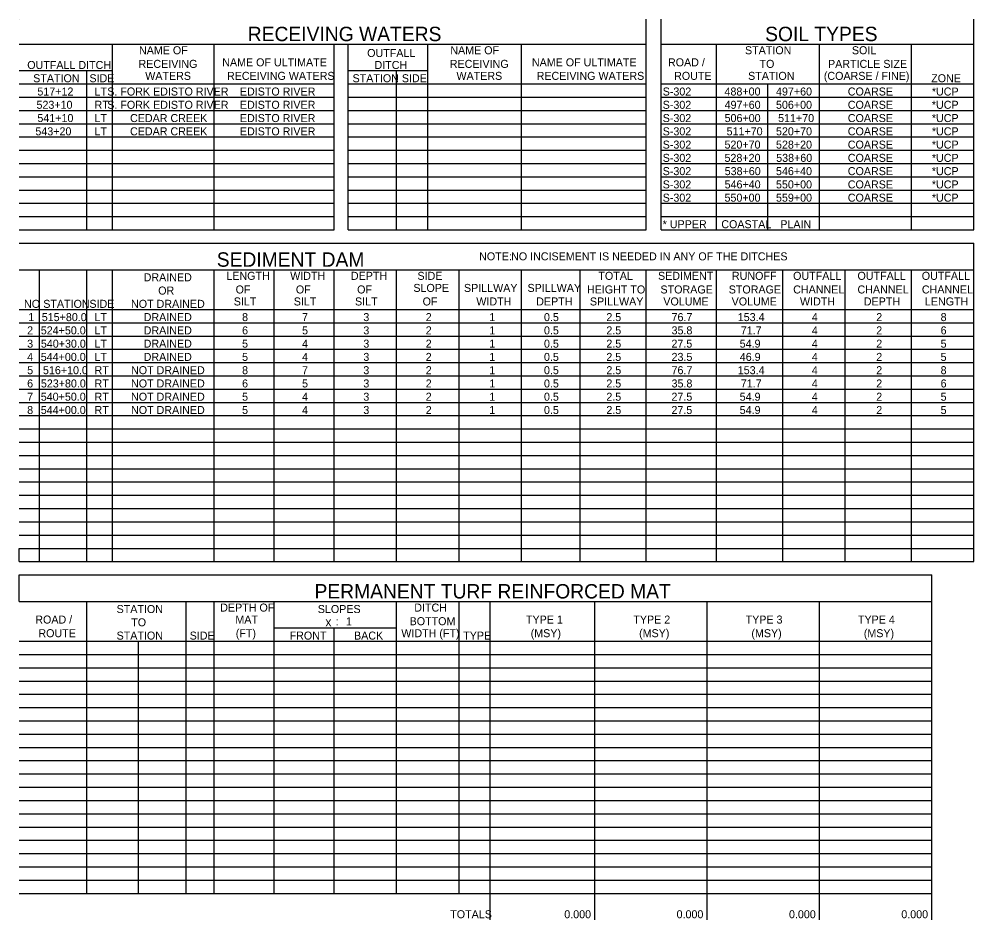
# Model space of a CAD drawing. Extents: x 17139 to 21295, y 12843 to 18076.
# Drawn here: x 19644 to 20688, y 12843 to 13827 of the extents above; entities that cross this region are included whole.
import ezdxf

# ---------------------------------------------------------------- set-up
doc = ezdxf.new("R2010")
doc.units = 0
doc.layers.add('Level 1', color=7, linetype='Continuous')
doc.layers.add('Level 3', color=7, linetype='Continuous')

msp = doc.modelspace()

# ---------------------------------------------------------------- linework, layer by layer
at = {"layer": 'Level 1'}
for p, q in [((20330.2, 13596.6), (20330.2, 13826.9)), ((20346.4, 13596.6), (20346.4, 13826.9)), ((20688.4, 13596.6), (20688.4, 13826.9)), ((19644.4, 13799.6), (20330.2, 13799.6)), ((19746.7, 13596.6), (19746.7, 13799.6)), ((19857.6, 13596.6), (19857.6, 13799.6)), ((19989, 13596.6), (19989, 13799.6)), ((20004.3, 13596.6), (20004.3, 13799.6)), ((20091.3, 13596.6), (20091.3, 13799.6)), ((20193.7, 13596.6), (20193.7, 13799.6)), ((20346.4, 13799.6), (20688.4, 13799.6)), ((20406.9, 13596.6), (20406.9, 13799.6)), ((20519.5, 13596.6), (20519.5, 13799.6)), ((20620.2, 13596.6), (20620.2, 13799.6)), ((19644.4, 13770.6), (19746.7, 13770.6)), ((19718.6, 13596.6), (19718.6, 13770.6)), ((20004.3, 13770.6), (20091.3, 13770.6)), ((20057.2, 13596.6), (20057.2, 13770.6)), ((19644.4, 13756.1), (19989, 13756.1)), ((19644.4, 13756.1), (19718.6, 13756.1)), ((20004.3, 13756.1), (20330.2, 13756.1)), ((20004.3, 13756.1), (20057.2, 13756.1)), ((20346.4, 13756.1), (20688.4, 13756.1)), ((20463.2, 13596.6), (20463.2, 13756.1)), ((19644.4, 13741.6), (19989, 13741.6)), ((20004.3, 13741.6), (20330.2, 13741.6)), ((20346.4, 13741.6), (20688.4, 13741.6)), ((19644.4, 13727.1), (19989, 13727.1)), ((20004.3, 13727.1), (20330.2, 13727.1)), ((20346.4, 13727.1), (20688.4, 13727.1)), ((19644.4, 13712.6), (19989, 13712.6)), ((20004.3, 13712.6), (20330.2, 13712.6)), ((20346.4, 13712.6), (20688.4, 13712.6)), ((19644.4, 13698.1), (19989, 13698.1)), ((20004.3, 13698.1), (20330.2, 13698.1)), ((20346.4, 13698.1), (20688.4, 13698.1)), ((19644.4, 13683.6), (19989, 13683.6)), ((20004.3, 13683.6), (20330.2, 13683.6)), ((20346.4, 13683.6), (20688.4, 13683.6)), ((19644.4, 13669.1), (19989, 13669.1)), ((20004.3, 13669.1), (20330.2, 13669.1)), ((20346.4, 13669.1), (20688.4, 13669.1)), ((19644.4, 13654.6), (19989, 13654.6)), ((20004.3, 13654.6), (20330.2, 13654.6)), ((20346.4, 13654.6), (20688.4, 13654.6)), ((19644.4, 13640.1), (19989, 13640.1)), ((20004.3, 13640.1), (20330.2, 13640.1)), ((20346.4, 13640.1), (20688.4, 13640.1)), ((19644.4, 13625.6), (19989, 13625.6)), ((20004.3, 13625.6), (20330.2, 13625.6)), ((20346.4, 13625.6), (20688.4, 13625.6)), ((19644.4, 13611.1), (19989, 13611.1)), ((20004.3, 13611.1), (20330.2, 13611.1)), ((20346.4, 13611.1), (20688.4, 13611.1)), ((19644.4, 13596.6), (19989, 13596.6)), ((20004.3, 13596.6), (20330.2, 13596.6)), ((20346.4, 13596.6), (20688.4, 13596.6)), ((19644.4, 13582.1), (20688.4, 13582.1)), ((20688.4, 13234.1), (20688.4, 13582.1)), ((19644.4, 13553.1), (20688.4, 13553.1)), ((19666.6, 13234.1), (19666.6, 13553.1)), ((19718.6, 13234.1), (19718.6, 13553.1)), ((19746.7, 13234.1), (19746.7, 13553.1)), ((19857.6, 13234.1), (19857.6, 13553.1)), ((19923.3, 13234.1), (19923.3, 13553.1)), ((19989, 13234.1), (19989, 13553.1)), ((20057.2, 13234.1), (20057.2, 13553.1)), ((20125.4, 13234.1), (20125.4, 13553.1)), ((20193.7, 13234.1), (20193.7, 13553.1)), ((20257.7, 13234.1), (20257.7, 13553.1)), ((20330.2, 13234.1), (20330.2, 13553.1)), ((20406.9, 13234.1), (20406.9, 13553.1)), ((20479.4, 13234.1), (20479.4, 13553.1)), ((20547.7, 13234.1), (20547.7, 13553.1)), ((20620.2, 13234.1), (20620.2, 13553.1)), ((19644.4, 13509.6), (20688.4, 13509.6)), ((19857.6, 13509.6), (20688.4, 13509.6)), ((19644.4, 13495.1), (20688.4, 13495.1)), ((19644.4, 13480.6), (20688.4, 13480.6)), ((19644.4, 13466.1), (20688.4, 13466.1)), ((19644.4, 13451.6), (20688.4, 13451.6)), ((19644.4, 13437.1), (20688.4, 13437.1)), ((19644.4, 13422.6), (20688.4, 13422.6)), ((19644.4, 13408.1), (20688.4, 13408.1)), ((19644.4, 13393.6), (20688.4, 13393.6)), ((19644.4, 13379.1), (20688.4, 13379.1)), ((19644.4, 13364.6), (20688.4, 13364.6)), ((19644.4, 13350.1), (20688.4, 13350.1)), ((19644.4, 13335.6), (20688.4, 13335.6)), ((19644.4, 13321.1), (20688.4, 13321.1)), ((19644.4, 13306.6), (20688.4, 13306.6)), ((19644.4, 13292.1), (20688.4, 13292.1)), ((19644.4, 13277.6), (20688.4, 13277.6)), ((19644.4, 13263.1), (20688.4, 13263.1)), ((19644.4, 13234.1), (19644.4, 13248.6)), ((19644.4, 13248.6), (20688.4, 13248.6)), ((19644.4, 13234.1), (20688.4, 13234.1)), ((19644.4, 13190.6), (19644.4, 13219.6)), ((19644.4, 13219.6), (20642.3, 13219.6)), ((20642.3, 12842.6), (20642.3, 13219.6)), ((19644.4, 13190.6), (20642.3, 13190.6)), ((19718.6, 12871.6), (19718.6, 13190.6)), ((19826.9, 12871.6), (19826.9, 13190.6)), ((19857.6, 12871.6), (19857.6, 13190.6)), ((19923.3, 12871.6), (19923.3, 13190.6)), ((20057.2, 12871.6), (20057.2, 13190.6)), ((20125.4, 12871.6), (20125.4, 13190.6)), ((20159.6, 12842.6), (20159.6, 13190.6)), ((20273.9, 12842.6), (20273.9, 13190.6)), ((20396.7, 12842.6), (20396.7, 13190.6)), ((20519.5, 12842.6), (20519.5, 13190.6)), ((19923.3, 13161.6), (20057.2, 13161.6)), ((19989, 12871.6), (19989, 13161.6)), ((19644.4, 13147.1), (20642.3, 13147.1)), ((19774.9, 12871.6), (19774.9, 13147.1)), ((19826.9, 13147.1), (20057.2, 13147.1)), ((20057.2, 13147.1), (20642.3, 13147.1)), ((19644.4, 13132.6), (20642.3, 13132.6)), ((19644.4, 13118.1), (20642.3, 13118.1)), ((19644.4, 13103.6), (20642.3, 13103.6)), ((19644.4, 13089.1), (20642.3, 13089.1)), ((19644.4, 13074.6), (20642.3, 13074.6)), ((19644.4, 13060.1), (20642.3, 13060.1)), ((19644.4, 13045.6), (20642.3, 13045.6)), ((19644.4, 13031.1), (20642.3, 13031.1)), ((19644.4, 13016.6), (20642.3, 13016.6)), ((19644.4, 13002.1), (20642.3, 13002.1)), ((19644.4, 12987.6), (20642.3, 12987.6)), ((19644.4, 12973.1), (20642.3, 12973.1)), ((19644.4, 12958.6), (20642.3, 12958.6)), ((19644.4, 12944.1), (20642.3, 12944.1)), ((19644.4, 12929.6), (20642.3, 12929.6)), ((19644.4, 12915.1), (20642.3, 12915.1)), ((19644.4, 12900.6), (20642.3, 12900.6)), ((19644.4, 12886.1), (20642.3, 12886.1)), ((19644.4, 12871.6), (20642.3, 12871.6))]:
    msp.add_line(p, q, dxfattribs=at)
at = {"layer": 'Level 3'}
msp.add_line((19644.4, 13826.9), (19644.4, 13826.9), dxfattribs=at)

# ---------------------------------------------------------------- texts
at = {"layer": 'Level 1'}
for s, height, p in [('RECEIVING WATERS', 15.747, (19894.4, 13802.8)), ('SOIL TYPES', 15.75, (20460.1, 13802.8)), ('NAME OF ', 8.75, (19775.5, 13788.5)), ('OUTFALL', 8.75, (20025, 13785.5)), ('NAME OF ', 8.75, (20115.9, 13788.5)), ('STATION ', 8.75, (20438.1, 13788.5)), ('SOIL ', 8.75, (20555, 13788.5)), ('OUTFALL DITCH', 8.748, (19653.3, 13772.4)), ('RECEIVING', 8.75, (19775, 13773.6)), ('NAME OF ULTIMATE ', 8.748, (19866.5, 13775.3)), ('DITCH', 8.75, (20033, 13772.4)), ('RECEIVING', 8.75, (20115.3, 13773.6)), ('NAME OF ULTIMATE ', 8.748, (20205.1, 13775.3)), ('ROAD / ', 8.75, (20353.9, 13775.3)), ('TO ', 8.75, (20454, 13773.6)), ('PARTICLE SIZE', 8.748, (20528.9, 13773.6)), ('STATION', 8.75, (19659.8, 13757.9)), ('SIDE', 8.75, (19721.3, 13757.9)), ('WATERS', 8.75, (19782.3, 13760.5)), ('RECEIVING WATERS', 8.748, (19871.7, 13760.5)), ('STATION', 8.75, (20009, 13757.9)), ('SIDE', 8.75, (20062.9, 13757.9)), ('WATERS', 8.75, (20122.6, 13760.5)), ('RECEIVING WATERS', 8.748, (20210.3, 13760.5)), ('ROUTE', 8.75, (20360.6, 13760.5)), ('STATION', 8.75, (20441.5, 13760.5)), ('(COARSE / FINE)', 8.748, (20524.3, 13760.5)), ('ZONE', 8.75, (20641.7, 13757.9)), ('517+12', 8.75, (19664.4, 13743.4)), ('LT', 8.75, (19726.9, 13743.4)), ('S. FORK EDISTO RIVER', 8.748, (19740.8, 13743.4)), ('EDISTO RIVER', 8.748, (19885.8, 13743.4)), ('S-302', 8.75, (20348.1, 13743.4)), ('488+00', 8.75, (20415.7, 13743.4)), ('497+60', 8.75, (20472, 13743.4)), ('COARSE', 8.75, (20550.5, 13743.4)), ('*UCP', 8.75, (20642.4, 13743.4)), ('523+10', 8.75, (19663.4, 13728.9)), ('RT', 8.75, (19726.9, 13728.9)), ('S. FORK EDISTO RIVER', 8.748, (19740.8, 13728.9)), ('EDISTO RIVER', 8.748, (19885.8, 13728.9)), ('S-302', 8.75, (20348.1, 13728.9)), ('497+60', 8.75, (20415.8, 13728.9)), ('506+00', 8.75, (20472, 13728.9)), ('COARSE', 8.75, (20550.5, 13728.9)), ('*UCP', 8.75, (20642.4, 13728.9)), ('541+10', 8.75, (19664.4, 13714.4)), ('LT', 8.75, (19726.9, 13714.4)), ('CEDAR CREEK', 8.748, (19765.7, 13714.4)), ('EDISTO RIVER', 8.748, (19885.8, 13714.4)), ('S-302', 8.75, (20348.1, 13714.4)), ('506+00', 8.75, (20415.8, 13714.4)), ('511+70', 8.75, (20474.3, 13714.4)), ('COARSE', 8.75, (20550.5, 13714.4)), ('*UCP', 8.75, (20642.4, 13714.4)), ('543+20', 8.75, (19662.2, 13699.9)), ('LT', 8.75, (19726.9, 13699.9)), ('CEDAR CREEK', 8.748, (19765.7, 13699.9)), ('EDISTO RIVER', 8.748, (19885.8, 13699.9)), ('S-302', 8.75, (20348.1, 13699.9)), ('511+70', 8.75, (20418, 13699.9)), ('520+70', 8.75, (20472, 13699.9)), ('COARSE', 8.75, (20550.5, 13699.9)), ('*UCP', 8.75, (20642.4, 13699.9)), ('S-302', 8.75, (20348.1, 13685.4)), ('520+70', 8.75, (20415.7, 13685.4)), ('528+20', 8.75, (20472, 13685.4)), ('COARSE', 8.75, (20550.5, 13685.4)), ('*UCP', 8.75, (20642.4, 13685.4)), ('S-302', 8.75, (20348.1, 13670.9)), ('528+20', 8.75, (20415.7, 13670.9)), ('538+60', 8.75, (20472.2, 13670.9)), ('COARSE', 8.75, (20550.5, 13670.9)), ('*UCP', 8.75, (20642.4, 13670.9)), ('S-302', 8.75, (20348.1, 13656.4)), ('538+60', 8.75, (20415.9, 13656.4)), ('546+40', 8.75, (20472, 13656.4)), ('COARSE', 8.75, (20550.5, 13656.4)), ('*UCP', 8.75, (20642.4, 13656.4)), ('S-302', 8.75, (20348.1, 13641.9)), ('546+40', 8.75, (20415.8, 13641.9)), ('550+00', 8.75, (20472, 13641.9)), ('COARSE', 8.75, (20550.5, 13641.9)), ('*UCP', 8.75, (20642.4, 13641.9)), ('S-302', 8.75, (20348.1, 13627.4)), ('550+00', 8.75, (20415.7, 13627.4)), ('559+00', 8.75, (20472, 13627.4)), ('COARSE', 8.75, (20550.5, 13627.4)), ('*UCP', 8.75, (20642.4, 13627.4)), ('* UPPER', 8.75, (20348.1, 13598.4)), ('COASTAL', 8.75, (20412.2, 13598.4)), ('PLAIN', 8.75, (20476.7, 13598.4)), ('SEDIMENT DAM          ', 15.747, (19860.5, 13556.3)), ('NOTE:', 8.75, (20147.4, 13563.3)), (' NO INCISEMENT IS NEEDED IN ANY OF THE DITCHES', 8.748, (20179.1, 13563.3)), ('DRAINED', 8.75, (19780.6, 13540.4)), ('LENGTH', 8.75, (19871, 13542)), ('WIDTH', 8.75, (19940.8, 13542)), ('DEPTH', 8.75, (20007.2, 13542)), ('SIDE', 8.75, (20080, 13542)), ('TOTAL', 8.75, (20277.8, 13542)), ('SEDIMENT', 8.75, (20343, 13542)), ('RUNOFF', 8.75, (20423.8, 13542)), ('OUTFALL', 8.75, (20490.7, 13542)), ('OUTFALL', 8.75, (20561.1, 13542)), ('OUTFALL', 8.75, (20631.4, 13542)), ('OR', 8.75, (19796.5, 13525.9)), (' OF ', 8.75, (19877.9, 13527.1)), ('OF ', 8.75, (19947, 13527.1)), ('OF ', 8.75, (20014, 13527.1)), ('SLOPE', 8.75, (20075.5, 13528.8)), ('SPILLWAY ', 8.75, (20130.8, 13528.8)), ('SPILLWAY', 8.75, (20200.3, 13528.8)), ('HEIGHT TO', 8.75, (20265.3, 13527.1)), ('STORAGE', 8.75, (20345.7, 13527.1)), ('STORAGE', 8.75, (20420.3, 13527.1)), ('CHANNEL', 8.75, (20490.8, 13527.1)), ('CHANNEL', 8.75, (20561.1, 13527.1)), ('CHANNEL', 8.75, (20631.5, 13527.1)), ('NO', 8.75, (19649.8, 13511.4)), ('STATION', 8.75, (19670.8, 13511.4)), ('SIDE', 8.75, (19721.3, 13511.4)), ('NOT DRAINED', 8.748, (19766.8, 13511.4)), ('SILT', 8.75, (19879.1, 13514)), ('SILT', 8.75, (19944.7, 13514)), ('SILT', 8.75, (20011.7, 13514)), ('OF', 8.75, (20085.6, 13514)), ('WIDTH', 8.75, (20144.3, 13514)), ('DEPTH', 8.75, (20209.8, 13514)), ('SPILLWAY', 8.75, (20268.5, 13514)), ('VOLUME', 8.75, (20348.8, 13514)), ('VOLUME', 8.75, (20423.5, 13514)), ('WIDTH', 8.75, (20498.2, 13514)), ('DEPTH', 8.75, (20568, 13514)), ('LENGTH', 8.75, (20634.8, 13514)), ('1', 8.75, (19654.4, 13496.9)), ('515+80.0', 8.75, (19669.2, 13496.9)), ('LT', 8.75, (19726.9, 13496.9)), ('DRAINED', 8.75, (19780.6, 13496.9)), ('8', 8.75, (19888.2, 13496.9)), ('7', 8.75, (19953.8, 13496.9)), ('3', 8.75, (20020.8, 13496.9)), ('2', 8.75, (20089, 13496.9)), ('1', 8.75, (20158.5, 13496.9)), ('0.5', 8.75, (20218.3, 13496.9)), ('2.5', 8.75, (20286.5, 13496.9)), ('76.7', 8.75, (20357.8, 13496.9)), ('153.4', 8.75, (20430.2, 13496.9)), ('4', 8.75, (20511.2, 13496.9)), ('2', 8.75, (20581.6, 13496.9)), ('8', 8.75, (20652, 13496.9)), ('2', 8.75, (19653.2, 13482.4)), ('524+50.0', 8.75, (19668.1, 13482.4)), ('LT', 8.75, (19726.9, 13482.4)), ('DRAINED', 8.75, (19780.6, 13482.4)), ('6', 8.75, (19888.2, 13482.4)), ('5', 8.75, (19953.8, 13482.4)), ('3', 8.75, (20020.8, 13482.4)), ('2', 8.75, (20089, 13482.4)), ('1', 8.75, (20158.5, 13482.4)), ('0.5', 8.75, (20218.3, 13482.4)), ('2.5', 8.75, (20286.5, 13482.4)), ('35.8', 8.75, (20357.8, 13482.4)), ('71.7', 8.75, (20433.5, 13482.4)), ('4', 8.75, (20511.2, 13482.4)), ('2', 8.75, (20581.6, 13482.4)), ('6', 8.75, (20652, 13482.4)), ('3', 8.75, (19653.2, 13467.9)), ('540+30.0', 8.75, (19668.2, 13467.9)), ('LT', 8.75, (19726.9, 13467.9)), ('DRAINED', 8.75, (19780.6, 13467.9)), ('5', 8.75, (19888.2, 13467.9)), ('4', 8.75, (19953.8, 13467.9)), ('3', 8.75, (20020.8, 13467.9)), ('2', 8.75, (20089, 13467.9)), ('1', 8.75, (20158.5, 13467.9)), ('0.5', 8.75, (20218.3, 13467.9)), ('2.5', 8.75, (20286.5, 13467.9)), ('27.5', 8.75, (20357.7, 13467.9)), ('54.9', 8.75, (20432.3, 13467.9)), ('4', 8.75, (20511.2, 13467.9)), ('2', 8.75, (20581.6, 13467.9)), ('5', 8.75, (20652, 13467.9)), ('4', 8.75, (19653.2, 13453.4)), ('544+00.0', 8.75, (19668.1, 13453.4)), ('LT', 8.75, (19726.9, 13453.4)), ('DRAINED', 8.75, (19780.6, 13453.4)), ('5', 8.75, (19888.2, 13453.4)), ('4', 8.75, (19953.8, 13453.4)), ('3', 8.75, (20020.8, 13453.4)), ('2', 8.75, (20089, 13453.4)), ('1', 8.75, (20158.5, 13453.4)), ('0.5', 8.75, (20218.3, 13453.4)), ('2.5', 8.75, (20286.5, 13453.4)), ('23.5', 8.75, (20357.8, 13453.4)), ('46.9', 8.75, (20432.4, 13453.4)), ('4', 8.75, (20511.2, 13453.4)), ('2', 8.75, (20581.6, 13453.4)), ('5', 8.75, (20652, 13453.4)), ('5', 8.75, (19653.2, 13438.9)), ('516+10.0', 8.75, (19670.5, 13438.9)), ('RT', 8.75, (19726.9, 13438.9)), ('NOT DRAINED', 8.748, (19766.8, 13438.9)), ('8', 8.75, (19888.2, 13438.9)), ('7', 8.75, (19953.8, 13438.9)), ('3', 8.75, (20020.8, 13438.9)), ('2', 8.75, (20089, 13438.9)), ('1', 8.75, (20158.5, 13438.9)), ('0.5', 8.75, (20218.3, 13438.9)), ('2.5', 8.75, (20286.5, 13438.9)), ('76.7', 8.75, (20357.8, 13438.9)), ('153.4', 8.75, (20430.2, 13438.9)), ('4', 8.75, (20511.2, 13438.9)), ('2', 8.75, (20581.6, 13438.9)), ('8', 8.75, (20652, 13438.9)), ('6', 8.75, (19653.2, 13424.4)), ('523+80.0', 8.75, (19668.2, 13424.4)), ('RT', 8.75, (19726.9, 13424.4)), ('NOT DRAINED', 8.748, (19766.8, 13424.4)), ('6', 8.75, (19888.2, 13424.4)), ('5', 8.75, (19953.8, 13424.4)), ('3', 8.75, (20020.8, 13424.4)), ('2', 8.75, (20089, 13424.4)), ('1', 8.75, (20158.5, 13424.4)), ('0.5', 8.75, (20218.3, 13424.4)), ('2.5', 8.75, (20286.5, 13424.4)), ('35.8', 8.75, (20357.8, 13424.4)), ('71.7', 8.75, (20433.5, 13424.4)), ('4', 8.75, (20511.2, 13424.4)), ('2', 8.75, (20581.6, 13424.4)), ('6', 8.75, (20652, 13424.4)), ('7', 8.75, (19653.2, 13409.9)), ('540+50.0', 8.75, (19668.1, 13409.9)), ('RT', 8.75, (19726.9, 13409.9)), ('NOT DRAINED', 8.748, (19766.8, 13409.9)), ('5', 8.75, (19888.2, 13409.9)), ('4', 8.75, (19953.8, 13409.9)), ('3', 8.75, (20020.8, 13409.9)), ('2', 8.75, (20089, 13409.9)), ('1', 8.75, (20158.5, 13409.9)), ('0.5', 8.75, (20218.3, 13409.9)), ('2.5', 8.75, (20286.5, 13409.9)), ('27.5', 8.75, (20357.7, 13409.9)), ('54.9', 8.75, (20432.3, 13409.9)), ('4', 8.75, (20511.2, 13409.9)), ('2', 8.75, (20581.6, 13409.9)), ('5', 8.75, (20652, 13409.9)), ('8', 8.75, (19653.2, 13395.4)), ('544+00.0', 8.75, (19668.1, 13395.4)), ('RT', 8.75, (19726.9, 13395.4)), ('NOT DRAINED', 8.748, (19766.8, 13395.4)), ('5', 8.75, (19888.2, 13395.4)), ('4', 8.75, (19953.8, 13395.4)), ('3', 8.75, (20020.8, 13395.4)), ('2', 8.75, (20089, 13395.4)), ('1', 8.75, (20158.5, 13395.4)), ('0.5', 8.75, (20218.3, 13395.4)), ('2.5', 8.75, (20286.5, 13395.4)), ('27.5', 8.75, (20357.7, 13395.4)), ('54.9', 8.75, (20432.3, 13395.4)), ('4', 8.75, (20511.2, 13395.4)), ('2', 8.75, (20581.6, 13395.4)), ('5', 8.75, (20652, 13395.4)), ('PERMANENT TURF REINFORCED MAT', 15.747, (19967.4, 13193.8)), ('STATION', 8.75, (19751, 13177.9)), ('DEPTH OF', 8.75, (19864.3, 13179.5)), ('SLOPES', 8.75, (19971, 13177.9)), ('DITCH', 8.75, (20076.5, 13179.5)), ('ROAD /', 8.75, (19662.1, 13166.4)), ('TO', 8.75, (19767, 13163.4)), ('MAT', 8.75, (19880.9, 13166.4)), ('x', 9.62, (19979.4, 13163.5)), (' :', 8.75, (19987.3, 13164.4)), (' 1', 8.75, (19998.5, 13164.4)), ('BOTTOM', 8.75, (20071.4, 13164.6)), ('TYPE 1', 8.75, (20198.6, 13166.4)), ('TYPE 2', 8.75, (20316, 13166.4)), ('TYPE 3', 8.75, (20438.8, 13166.4)), ('TYPE 4', 8.75, (20561.6, 13166.4)), ('ROUTE', 8.75, (19665.5, 13151.5)), ('STATION', 8.75, (19751, 13148.9)), ('SIDE', 8.75, (19830.9, 13148.9)), ('(FT)', 8.75, (19881.3, 13151.5)), ('FRONT', 8.75, (19940.2, 13148.9)), ('BACK', 8.75, (20010.6, 13148.9)), ('WIDTH (FT)', 8.75, (20062.3, 13151.5)), ('TYPE', 8.75, (20130, 13148.9)), ('(MSY)', 8.75, (20203.8, 13151.5)), ('(MSY)', 8.75, (20322.3, 13151.5)), ('(MSY)', 8.75, (20445.1, 13151.5)), ('(MSY)', 8.75, (20568, 13151.5)), ('TOTALS', 8.75, (20115.8, 12844.4)), ('0.000', 8.75, (20240.5, 12844.4)), ('0.000', 8.75, (20363.3, 12844.4)), ('0.000', 8.75, (20486.2, 12844.4)), ('0.000', 8.75, (20609, 12844.4))]:
    msp.add_text(s, height=height, dxfattribs=at).set_placement(p)

doc.saveas('drawing.dxf')
